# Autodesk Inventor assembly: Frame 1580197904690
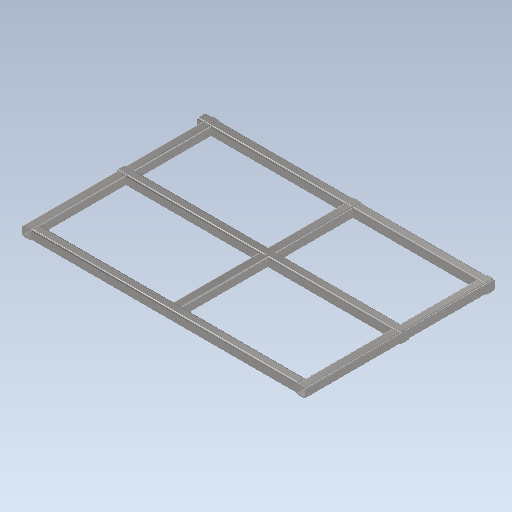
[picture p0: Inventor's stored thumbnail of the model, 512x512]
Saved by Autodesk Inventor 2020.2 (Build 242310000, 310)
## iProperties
_FrameDoc: Frame Assembly
_Version: 15.0.0
Created: 2020-01
Part Number: Frame 1580197904690
Document SubType Name: Assembly
Designer: thira
Author: thira
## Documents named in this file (8)
- F:\99.โปรแกรมอัดหน้าจอ\Synergysoft\FRAME\Frame_Generator\Frame\Assembly3\Frame\Frame 1580197904690.iam
- F:\99.โปรแกรมอัดหน้าจอ\Synergysoft\FRAME\Frame_Generator\Frame\Assembly3\Frame\Skeleton 1580197904691.ipt
- F:\99.โปรแกรมอัดหน้าจอ\Synergysoft\FRAME\Frame_Generator\Frame\Assembly3\Frame\ISO 40x40x4 1580197907087.ipt
- F:\99.โปรแกรมอัดหน้าจอ\Synergysoft\FRAME\Frame_Generator\Frame\Assembly3\Frame\ISO 40x40x4 1580197907088.ipt
- F:\99.โปรแกรมอัดหน้าจอ\Synergysoft\FRAME\Frame_Generator\Frame\Assembly3\Frame\ISO 40x40x4 1580197907089.ipt
- F:\99.โปรแกรมอัดหน้าจอ\Synergysoft\FRAME\Frame_Generator\Frame\Assembly3\Frame\ISO 40x40x4 1580197907090.ipt
- F:\99.โปรแกรมอัดหน้าจอ\Synergysoft\FRAME\Frame_Generator\Frame\Assembly3\Frame\ISO 40x40x4 1580197907091.ipt
- F:\99.โปรแกรมอัดหน้าจอ\Synergysoft\FRAME\Frame_Generator\Frame\Assembly3\Frame\ISO 40x40x4 1580197907092.ipt
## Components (7 placed, 2 different names)
1. Frame Reference Model
2. ISO 40x40x4:1
3. ISO 40x40x4:2
4. ISO 40x40x4:3
5. ISO 40x40x4:4
6. ISO 40x40x4:5
7. ISO 40x40x4:6
